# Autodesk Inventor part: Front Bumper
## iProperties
Shininess: 100.0
Angle Display Precision: 2
Document Length Units: 11269
Document Angle Units: 11279
Document Time Units: 11290
Document Mass Units: 11283
Document Length Units Precision: 3
Document Angle Units Precision: 2
Compacted: True
Company: Autodesk
Created: 2003-06
Part Number: Front Bumper
Document SubType Name: Modeling
Designer: Rodney Kerbyson
Description: Front Bumper
Density: 0.0
Volumn: 0.0
Area: 0.0
PropertySet Name: Model Information
Control State: 0
Master: False
Checked Out: False
Author: Rodney Kerbyson
Revision Number: 1
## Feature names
1. Extrusion1
2. Loft1
3. Sweep1
4. Mirror1
5. Extrusion2
6. Chamfer1
